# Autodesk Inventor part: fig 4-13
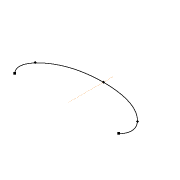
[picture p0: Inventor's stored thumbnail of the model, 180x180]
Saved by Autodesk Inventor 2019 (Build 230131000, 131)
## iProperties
Created: 2012-07
Part Number: fig 4-13
Material: Generic
Document SubType Name: Modeling
Designer: CADCIM
Density: 1 g/cm^3
Appearance: Default
Author: CADCIM
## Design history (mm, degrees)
sketch "Sketch1"
  geometry: L1 (0.121, 13.041)-(0.121, 1.483); L2 (-10.815, -1.576)-(-15.691, 3.573); L3 (-3.522, 10.439)-(3.764, 10.439); L4 (-14.873, 3.848)-(-11.149, 8.074); L5 (11.391, 8.074)-(15.115, 3.848); L6 (15.933, 3.573)-(11.057, -1.576); A1 r 5.401 centre (-9.332, 4.712) between (-14.53, 3.248) and (-11.076, -0.399); A2 r 30.439 centre (0.121, -20) between (3.022, 10.3) and (-2.78, 10.3); A3 r 7.63 centre (-7.286, 0.917) between (-11.348, 7.376) and (-14.205, 4.133); A4 r 7.63 centre (7.528, 0.917) between (14.447, 4.133) and (11.59, 7.376); A5 r 5.401 centre (9.574, 4.712) between (11.318, -0.399) and (14.772, 3.248); 5 further points
  constraints: 12 end point, 10 symmetric about line, 8 midpoint, 5 centre point, 5 point on circle, 1 vertical, 19 other
